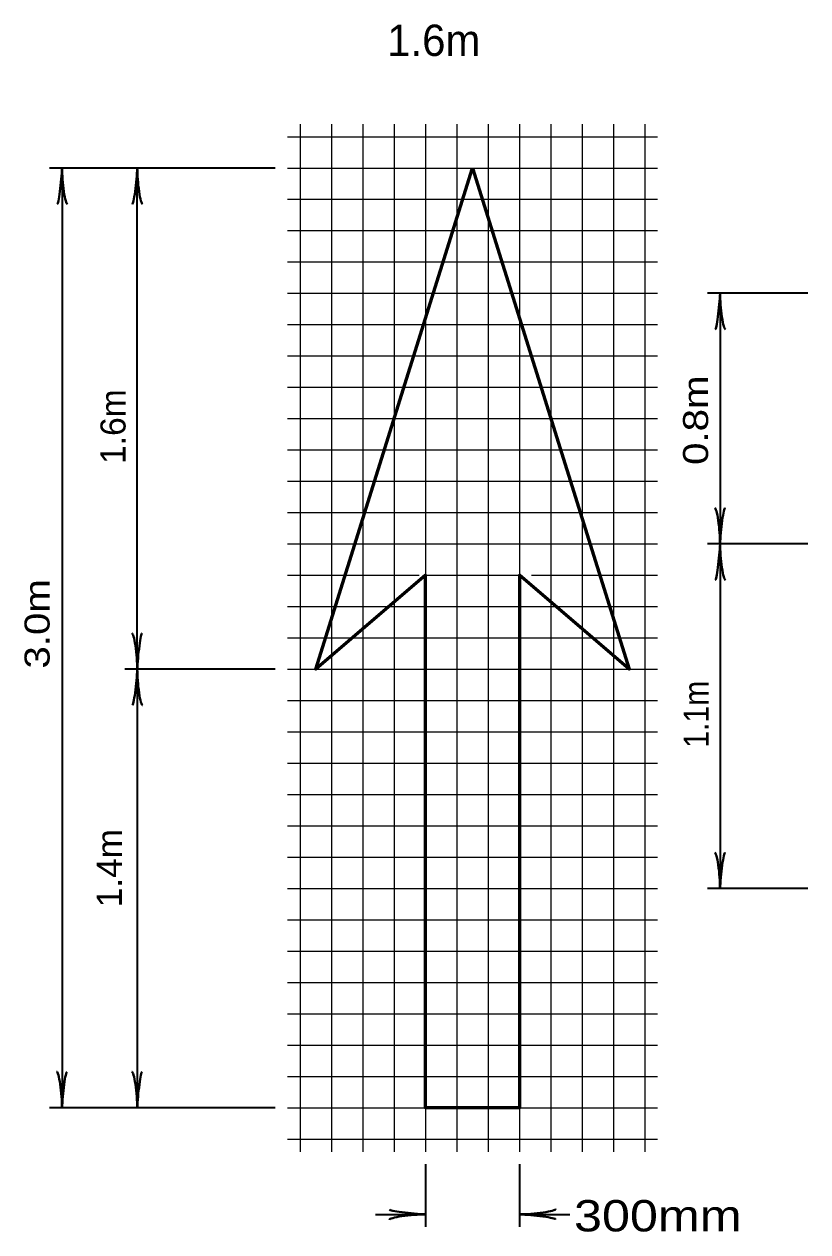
# Model space of a CAD drawing. Extents: x -96 to 617, y -65 to 388.
# Drawn here: x 112.1 to 174.6, y 128.7 to 225.1 of the extents above; entities that cross this region are included whole.
import ezdxf
from ezdxf.enums import TextEntityAlignment as Align

# ---------------------------------------------------------------- set-up
doc = ezdxf.new("R2010")
doc.units = 0
doc.layers.add('1', color=7, linetype='Continuous', lineweight=53)

msp = doc.modelspace()

# ---------------------------------------------------------------- linework, layer by layer
at = {"layer": '1', "lineweight": 25}
for p, q in [((134.079, 217.099), (134.079, 135.099)), ((136.579, 217.099), (136.579, 135.099)), ((139.079, 217.099), (139.079, 135.099)), ((141.579, 217.099), (141.579, 135.099)), ((144.079, 217.099), (144.079, 135.099)), ((146.579, 217.099), (146.579, 135.099)), ((149.079, 217.099), (149.079, 135.099)), ((151.579, 217.099), (151.579, 135.099)), ((154.079, 217.099), (154.079, 135.099)), ((156.579, 217.099), (156.579, 135.099)), ((159.079, 217.099), (159.079, 135.099)), ((161.579, 217.099), (161.579, 135.099)), ((133.079, 216.099), (162.579, 216.099)), ((133.079, 213.599), (146.579, 213.599)), ((146.579, 213.599), (149.079, 213.599)), ((149.079, 213.599), (162.579, 213.599)), ((133.079, 211.099), (162.579, 211.099)), ((133.079, 208.599), (162.579, 208.599)), ((133.079, 206.099), (162.579, 206.099)), ((133.079, 203.599), (162.579, 203.599)), ((133.079, 201.099), (162.579, 201.099)), ((133.079, 198.599), (162.579, 198.599)), ((133.079, 196.099), (162.579, 196.099)), ((133.079, 193.599), (162.579, 193.599)), ((133.079, 191.099), (162.579, 191.099)), ((133.079, 188.599), (162.579, 188.599)), ((133.079, 186.099), (162.579, 186.099)), ((133.079, 183.599), (162.579, 183.599)), ((133.079, 181.099), (143.559, 181.099)), ((144.079, 181.099), (151.579, 181.099)), ((152.528, 181.099), (162.579, 181.099)), ((133.079, 178.599), (162.579, 178.599)), ((133.079, 176.099), (162.579, 176.099)), ((133.079, 173.599), (134.079, 173.599)), ((134.079, 173.599), (136.579, 173.599)), ((136.579, 173.599), (159.079, 173.599)), ((159.079, 173.599), (161.579, 173.599)), ((161.579, 173.599), (162.579, 173.599)), ((133.079, 171.099), (162.579, 171.099)), ((133.079, 168.599), (162.579, 168.599)), ((133.079, 166.099), (162.579, 166.099)), ((133.079, 163.599), (162.579, 163.599)), ((133.079, 161.099), (162.579, 161.099)), ((133.079, 158.599), (162.579, 158.599)), ((133.079, 156.099), (162.579, 156.099)), ((133.079, 153.599), (162.579, 153.599)), ((133.079, 151.099), (162.579, 151.099)), ((133.079, 148.599), (162.579, 148.599)), ((133.079, 146.099), (162.579, 146.099)), ((133.079, 143.599), (162.579, 143.599)), ((133.079, 141.099), (162.579, 141.099)), ((133.079, 138.599), (162.579, 138.599)), ((133.079, 136.099), (162.579, 136.099))]:
    msp.add_line(p, q, dxfattribs=at)
at = {"layer": '1', "lineweight": 35}
for p, q in [((132.079, 213.599), (114.079, 213.599)), ((115.079, 213.599), (115.079, 138.599)), ((121.079, 173.599), (121.079, 213.599)), ((174.579, 203.599), (166.579, 203.599)), ((174.579, 183.599), (166.579, 183.599)), ((132.079, 173.599), (120.079, 173.599)), ((121.079, 173.599), (121.079, 138.599)), ((174.579, 156.099), (166.579, 156.099)), ((132.079, 138.599), (114.079, 138.599)), ((144.079, 134.099), (144.079, 129.099)), ((151.579, 134.099), (151.579, 129.099)), ((140.079, 130.099), (144.079, 130.099)), ((151.579, 130.099), (155.579, 130.099))]:
    msp.add_line(p, q, dxfattribs=at)
at = {"layer": '1'}
msp.add_lwpolyline([(147.829, 213.599), (160.329, 173.599), (151.579, 181.099), (151.579, 138.599), (144.079, 138.599), (144.079, 181.099), (135.329, 173.599)], close=True, dxfattribs=at)
at = {"layer": '1', "lineweight": 35}
msp.add_lwpolyline([(167.579, 203.599), (167.579, 183.599), (167.579, 156.099)], dxfattribs=at)
at = {"layer": '1', "lineweight": 40}
for centre, major_axis, ratio, start_param, end_param in [((114.867, 212.478), (0.176, 1.756), 0.07063, 3.140715, 5.41811), ((114.867, 212.478), (0.176, 1.756), 0.07063, 3.140715, 5.41811), ((115.355, 212.507), (-0.156, 1.786), 0.122415, 0.896353, 3.141593), ((115.355, 212.507), (-0.156, 1.786), 0.122415, 0.896353, 3.141593), ((120.867, 212.478), (0.176, 1.756), 0.07063, 3.140715, 5.41811), ((120.867, 212.478), (0.176, 1.756), 0.07063, 3.140715, 5.41811), ((121.355, 212.507), (-0.156, 1.786), 0.122415, 0.896353, 3.141593), ((121.355, 212.507), (-0.156, 1.786), 0.122415, 0.896353, 3.141593), ((167.367, 202.478), (0.176, 1.756), 0.07063, 3.140715, 5.41811), ((167.367, 202.478), (0.176, 1.756), 0.07063, 3.140715, 5.41811), ((167.855, 202.507), (-0.156, 1.786), 0.122415, 0.896353, 3.141593), ((167.855, 202.507), (-0.156, 1.786), 0.122415, 0.896353, 3.141593), ((167.302, 184.69), (0.156, -1.786), 0.122415, 0.896353, 3.141593), ((167.302, 184.69), (0.156, -1.786), 0.122415, 0.896353, 3.141593), ((167.79, 184.719), (-0.176, -1.756), 0.07063, 3.140715, 5.41811), ((167.79, 184.719), (-0.176, -1.756), 0.07063, 3.140715, 5.41811), ((167.367, 182.478), (0.176, 1.756), 0.07063, 3.140715, 5.41811), ((167.367, 182.478), (0.176, 1.756), 0.07063, 3.140715, 5.41811), ((167.855, 182.507), (-0.156, 1.786), 0.122415, 0.896353, 3.141593), ((167.855, 182.507), (-0.156, 1.786), 0.122415, 0.896353, 3.141593), ((120.802, 174.69), (0.156, -1.786), 0.122415, 0.896353, 3.141593), ((120.802, 174.69), (0.156, -1.786), 0.122415, 0.896353, 3.141593), ((121.29, 174.719), (-0.176, -1.756), 0.07063, 3.140715, 5.41811), ((121.29, 174.719), (-0.176, -1.756), 0.07063, 3.140715, 5.41811), ((120.867, 172.478), (0.176, 1.756), 0.07063, 3.140715, 5.41811), ((120.867, 172.478), (0.176, 1.756), 0.07063, 3.140715, 5.41811), ((121.355, 172.507), (-0.156, 1.786), 0.122415, 0.896353, 3.141593), ((121.355, 172.507), (-0.156, 1.786), 0.122415, 0.896353, 3.141593), ((167.302, 157.19), (0.156, -1.786), 0.122415, 0.896353, 3.141593), ((167.79, 157.219), (-0.176, -1.756), 0.07063, 3.140715, 5.41811), ((114.802, 139.69), (0.156, -1.786), 0.122415, 0.896353, 3.141593), ((114.802, 139.69), (0.156, -1.786), 0.122415, 0.896353, 3.141593), ((115.29, 139.719), (-0.176, -1.756), 0.07063, 3.140715, 5.41811), ((115.29, 139.719), (-0.176, -1.756), 0.07063, 3.140715, 5.41811), ((120.802, 139.69), (0.156, -1.786), 0.122415, 0.896353, 3.141593), ((120.802, 139.69), (0.156, -1.786), 0.122415, 0.896353, 3.141593), ((121.29, 139.719), (-0.176, -1.756), 0.07063, 3.140715, 5.41811), ((121.29, 139.719), (-0.176, -1.756), 0.07063, 3.140715, 5.41811), ((142.958, 130.31), (1.756, -0.176), 0.07063, 3.140715, 5.41811), ((142.958, 130.31), (1.756, -0.176), 0.07063, 3.140715, 5.41811), ((152.67, 130.375), (-1.786, -0.156), 0.122415, 0.896353, 3.141593), ((152.67, 130.375), (-1.786, -0.156), 0.122415, 0.896353, 3.141593), ((142.987, 129.822), (1.786, 0.156), 0.122415, 0.896353, 3.141593), ((142.987, 129.822), (1.786, 0.156), 0.122415, 0.896353, 3.141593), ((152.699, 129.887), (-1.756, 0.176), 0.07063, 3.140715, 5.41811), ((152.699, 129.887), (-1.756, 0.176), 0.07063, 3.140715, 5.41811)]:
    msp.add_ellipse(centre, major_axis=major_axis, ratio=ratio, start_param=start_param, end_param=end_param, dxfattribs=at)

# ---------------------------------------------------------------- texts
at = {"layer": '1'}
msp.add_text('1.6m', height=2.5, dxfattribs=at).set_placement((144.738, 222.541), align=Align.CENTER)
for s, width, p in [('0.8m', 1.2, (166.623, 193.474)), ('3.0m', 1.2, (114.088, 177.222)), ('1.1m', 0.9, (166.668, 170.007)), ('1.4m', 1.05, (119.851, 157.725))]:
    msp.add_text(s, height=2, rotation=90, dxfattribs=dict(at, width=width)).set_placement(p, align=Align.CENTER)
msp.add_text('1.6m', height=2, rotation=90, dxfattribs=at).set_placement((120.147, 192.961), align=Align.CENTER)
at = {"layer": '1', "width": 1.2}
msp.add_text('300mm', height=2.5, dxfattribs=at).set_placement((162.612, 128.739), align=Align.CENTER)

doc.saveas('drawing.dxf')
